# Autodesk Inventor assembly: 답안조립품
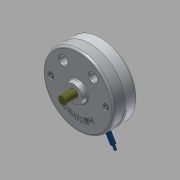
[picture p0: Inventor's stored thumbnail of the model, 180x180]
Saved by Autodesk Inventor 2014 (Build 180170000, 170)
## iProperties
Created: 2015-06
Part Number: 답안조립품
Document SubType Name: Assembly
Designer: MYHOME
Author: MYHOME
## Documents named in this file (10)
- C:\Documents and Settings\MYHOME\바탕 화면\450631V1047\답안조립품.iam
- C:\Documents and Settings\MYHOME\바탕 화면\450631V1047\본체.ipt
- C:\Documents and Settings\MYHOME\바탕 화면\450631V1047\덮개.ipt
- C:\Documents and Settings\MYHOME\바탕 화면\450631V1047\베어링62_22.ipt
- C:\Documents and Settings\MYHOME\바탕 화면\450631V1047\M10x35.ipt
- C:\Documents and Settings\MYHOME\바탕 화면\450631V1047\축.ipt
- C:\Documents and Settings\MYHOME\바탕 화면\450631V1047\멈춤링.ipt
- C:\Documents and Settings\MYHOME\바탕 화면\450631V1047\슬라이더2.ipt
- C:\Documents and Settings\MYHOME\바탕 화면\450631V1047\슬라이더.ipt
- C:\Documents and Settings\MYHOME\바탕 화면\450631V1047\평행핀.ipt
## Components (7 placed, 4 different names)
1. KS B 2023 62/22 - 22 x 50 x 14:1
2. KS B 2023 62/22 - 22 x 50 x 14:2
3. KS B 1336 22 x 1.2:1 — 각도:2
4. KS B 1336 22 x 1.2:2 — 각도:3
5. KS B 1320 B B 5 x  20:1
6. KS B 1003 - 미터 M 10 x 35:1
7. KS B 1003 - 미터 M 10 x 35:2
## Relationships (2: Angle 2)
- 각도:2 [Angle]: KS B 1336 22 x 1.2:1
- 각도:3 [Angle]: KS B 1336 22 x 1.2:2
